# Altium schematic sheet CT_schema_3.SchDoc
size 298 x 247 mm
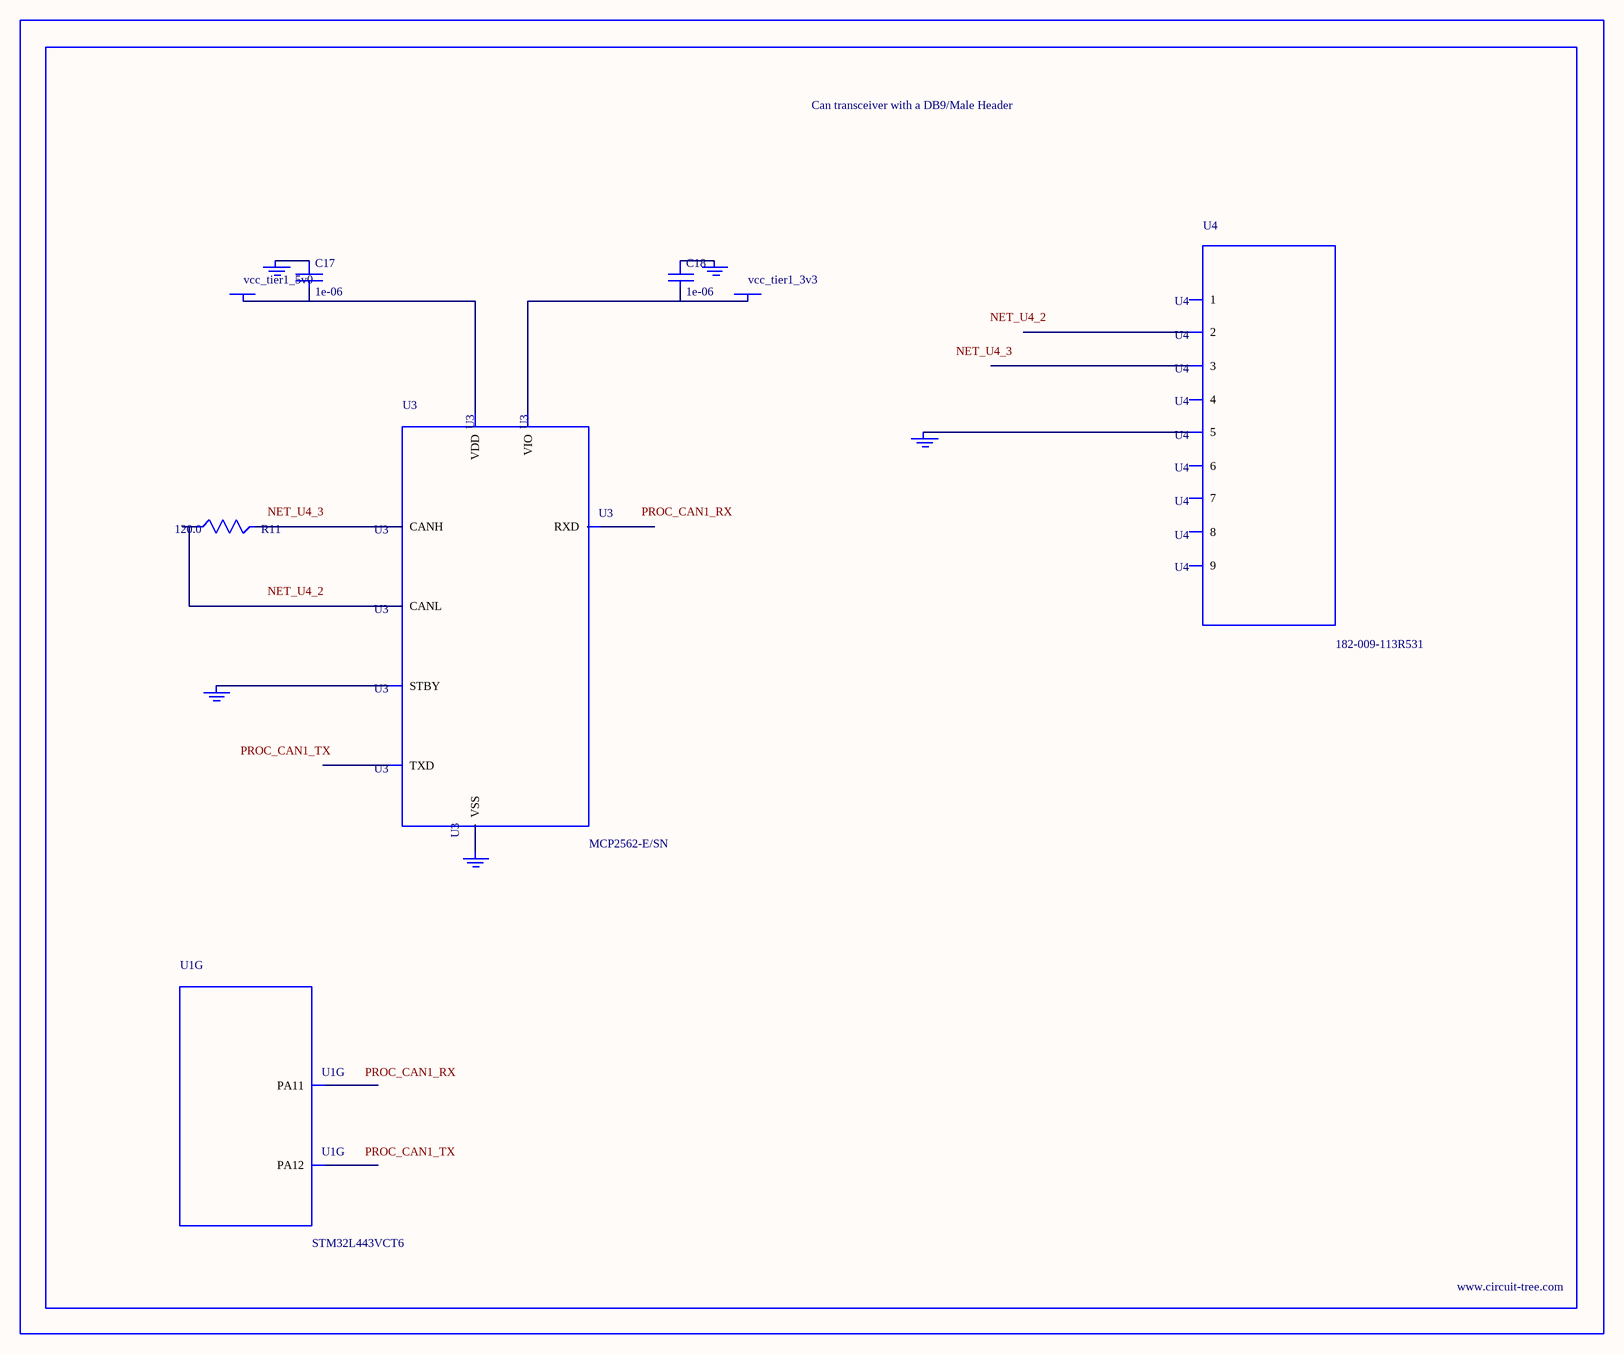
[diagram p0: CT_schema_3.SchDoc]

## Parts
BORDER2  (no value)
C17  1e-06  [C0603]
C18  1e-06  [C0603]
GND_INSTANCE_2_0  (no value)
GND_INSTANCE_2_1  (no value)
GND_INSTANCE_2_2  (no value)
GND_INSTANCE_2_3  (no value)
GND_INSTANCE_2_4  (no value)
POWER_INSTANCE_2_0  vcc_tier1_5v0
POWER_INSTANCE_2_1  vcc_tier1_3v3
R11  120.0  [R0603]
U1  STM32L443VCT6  [LQFP100]  (part G of 9)
U3  MCP2562-E/SN  [SOIC-8]
U4  182-009-113R531  [182-009-MALE]

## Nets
NetC17_1: C17.1 GND_INSTANCE_2_0.0(GND)
NetC17_2: C17.2 POWER_INSTANCE_2_0.0(PWR) U3.3(VDD)
NetC18_1: C18.1 GND_INSTANCE_2_1.0(GND)
NetC18_2: C18.2 POWER_INSTANCE_2_1.0(PWR) U3.5(VIO)
NetGND_INSTANCE_2_2_0: GND_INSTANCE_2_2.0(GND) U3.8(STBY)
NetGND_INSTANCE_2_3_0: GND_INSTANCE_2_3.0(GND) U3.2(VSS)
NetGND_INSTANCE_2_4_0: GND_INSTANCE_2_4.0(GND) U4.5
NetR11_1: R11.1 U3.6(CANL)
NetR11_2: R11.2 U3.7(CANH)

Not connected (* = marked no-connect by the designer): U1 70(PA11) 71(PA12); U3 1(TXD) 4(RXD); U4 1 2 3 4 6 7 8 9

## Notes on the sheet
- Labels drawn without touching a wire or pin: NET_U4_2, NET_U4_3, PROC_CAN1_RX, PROC_CAN1_TX

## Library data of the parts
BORDER2 = BORDER_PAGE2
C17 C18 = C0603C105K3RACTU
GND_INSTANCE_2_0-GND_INSTANCE_2_4 = GND
POWER_INSTANCE_2_0 POWER_INSTANCE_2_1 = PWR
R11 = RC0603JR-07120RL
